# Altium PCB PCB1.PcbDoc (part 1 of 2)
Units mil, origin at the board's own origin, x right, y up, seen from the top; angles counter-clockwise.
Board outline 2130 x 2330 mil, 2 copper layers (Top Layer, Bottom Layer); 110 components, 79 nets, 324 pads, 362 vias.
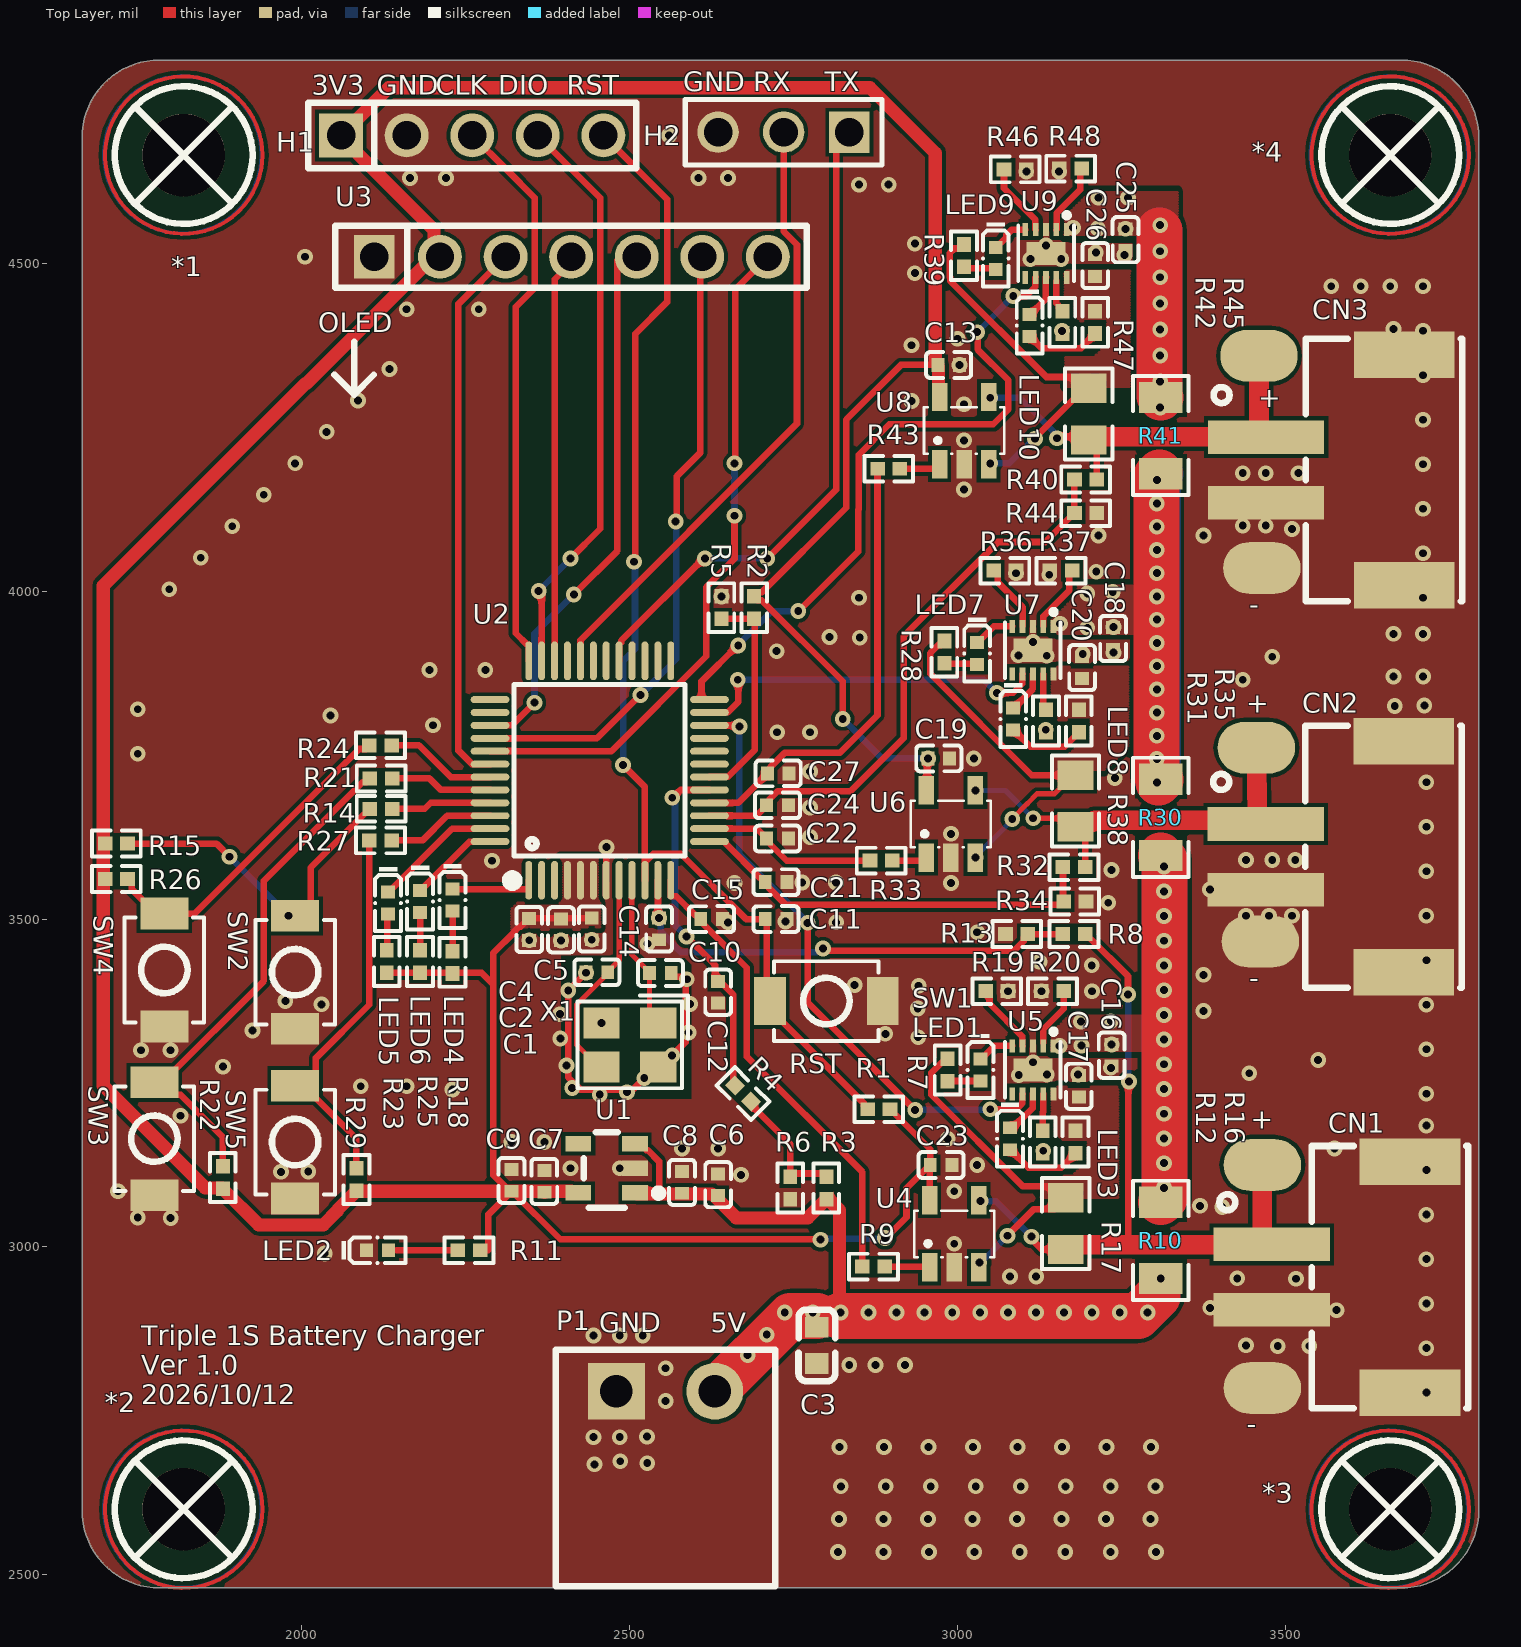
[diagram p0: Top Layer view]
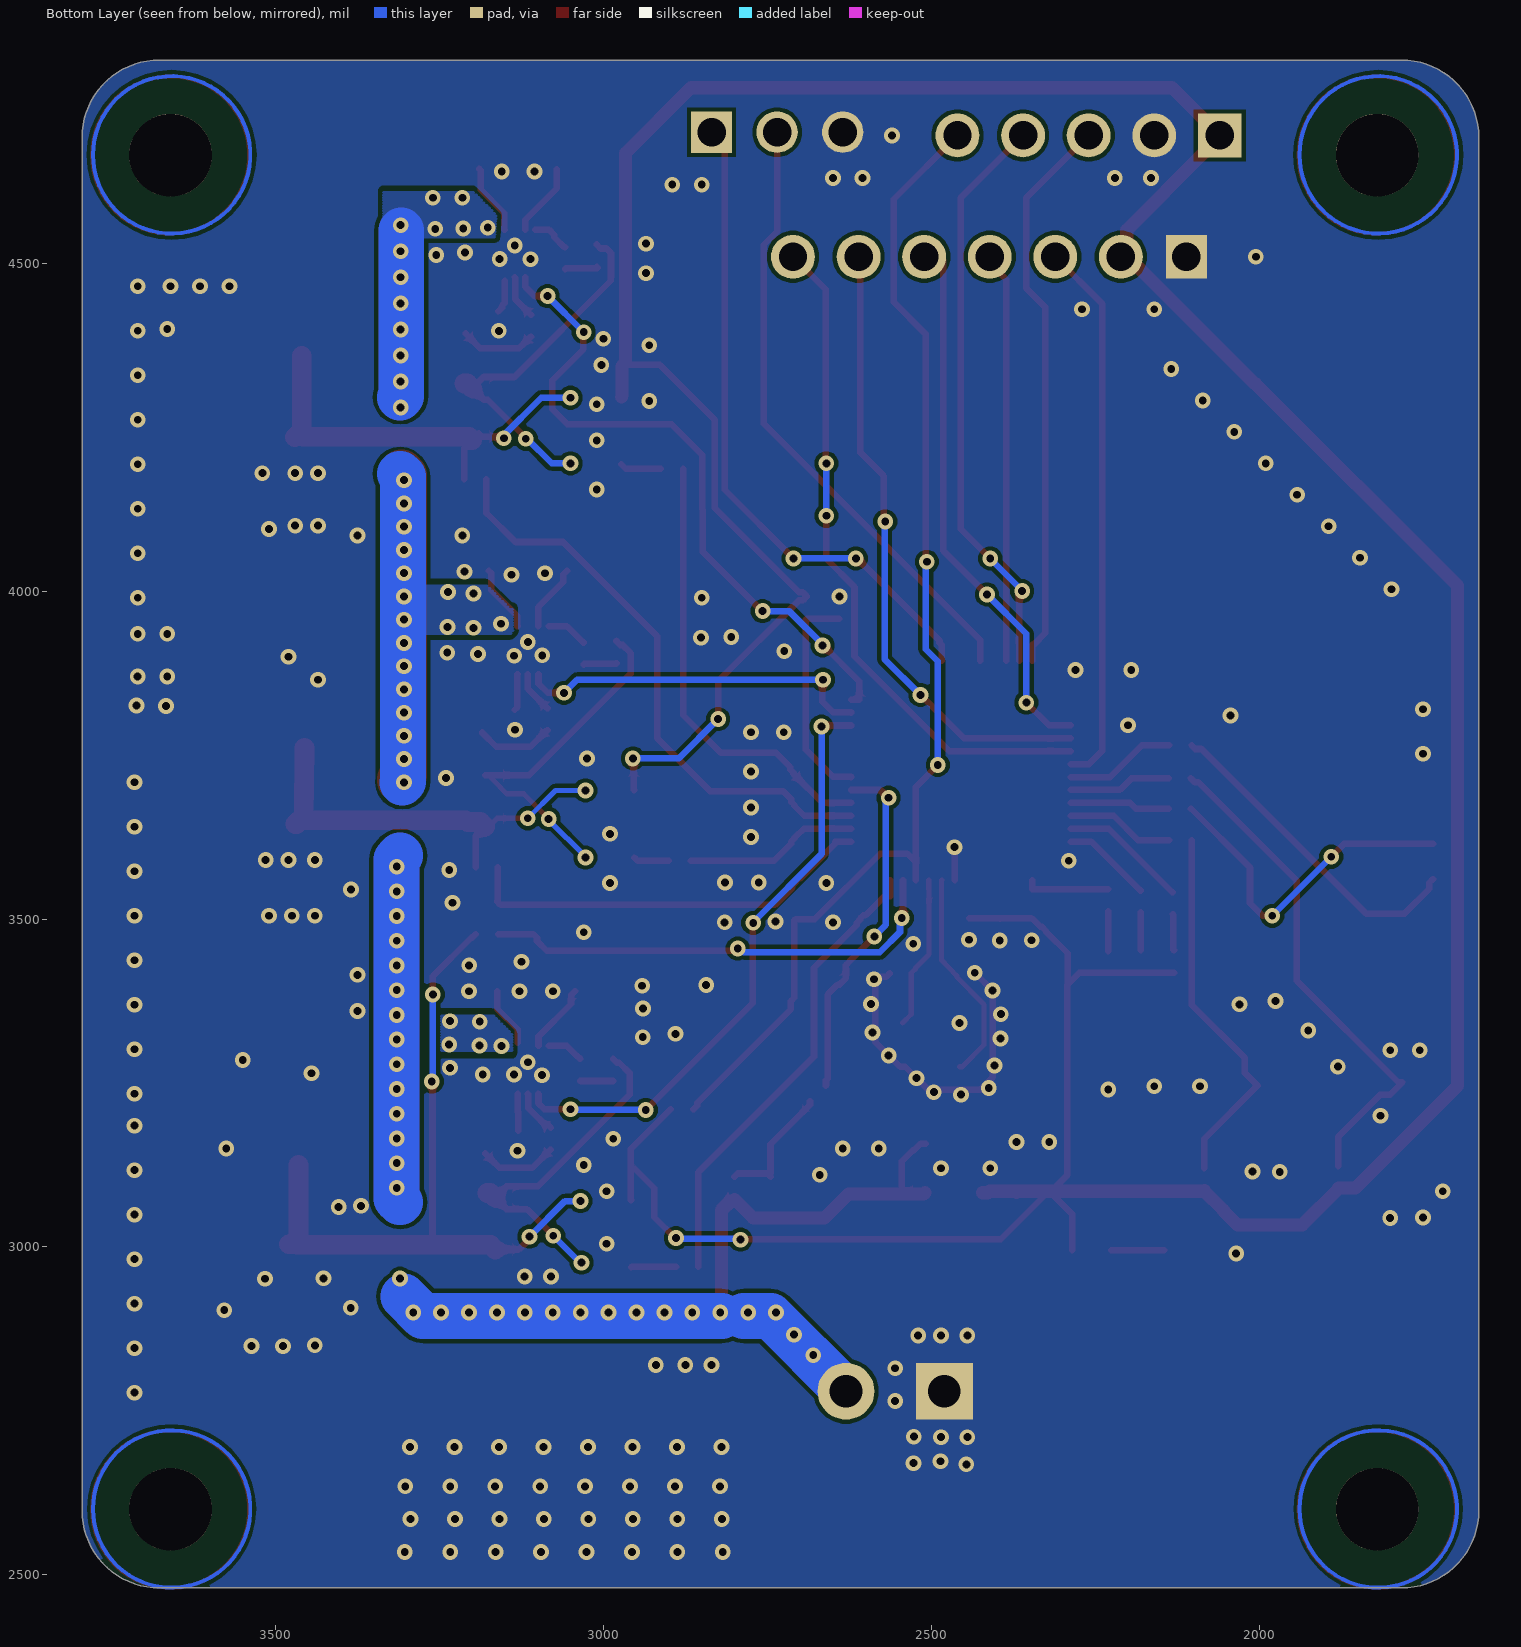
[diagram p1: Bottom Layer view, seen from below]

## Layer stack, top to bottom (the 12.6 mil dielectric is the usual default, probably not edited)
Top Solder: solder mask 0.4, Solder Resist, Dk 3.5
Top Layer: signal copper 1.4
Dielectric 1: dielectric 12.6, FR-4, Dk 4.8
Bottom Layer: signal copper 1.4
Bottom Solder: solder mask 0.4, Solder Resist, Dk 3.5

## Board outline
1665,2598.11 1665,4691.89 cw(c1783.11,4691.89) 1783.11,4810 3676.89,4810 cw(c3676.89,4691.89) 3795,4691.89 3795,2598.11 cw(c3676.89,2598.11) 3676.89,2480 1783.11,2480 cw(c1783.11,2598.11)

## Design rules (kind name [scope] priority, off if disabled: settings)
Clearance [All] p1: gap=6 ignorepadtopadclearanceinfootprint=FALSE except(4: Arc-Arc Arc-Track Track-Track; 6.9: Arc-Hole Track-Hole SMDPad-Hole THPad-Hole Via-Hole Fill-Hole Poly-Hole Region-Hole Text-Hole; 10: Fill-Text Poly-Text Region-Text)
ComponentClearance [All] p1: gap=0 collisioncheckmode=3 verticalgap=0 showdistances=FALSE
HoleSize [All] p1: absolutevalues=TRUE maxlimit=130 minlimit=1 maxpercent=80.000 minpercent=20.000
MinimumSolderMaskSliver [All] p1: minsoldermaskwidth=4
PlaneConnect [All] p1: planeconnectstyle=Direct reliefexpansion=20 reliefentries=4 reliefconductorwidth=10 reliefairgap=10
PolygonConnect [All] p1: connectstyle=Direct reliefconductorwidth=10 reliefentries=4 polygonreliefangle="90 Angle" airgapwidth=10
RoutingVias [All] p1: holewidth=28 width=50 viastyle="Through Hole" minholewidth=28 minwidth=50 maxholewidth=28 maxwidth=50
SilkToSilkClearance [All] p1: silktosilkclearance=2
SilkToSolderMaskClearance [IsPad] p1: minsilkscreentomaskgap=2 clearancetoexposedcopper=TRUE
SolderMaskExpansion [All] p1: expansion=0 istentingtop=FALSE
SupplyNets "Schematic Supply Nets_12" [InNet('5V_1')] p1: voltage=0.000
SupplyNets "Schematic Supply Nets_11" [InNet('5V_2')] p2: voltage=0.000
SupplyNets "Schematic Supply Nets_2" [InNet('5V_3')] p3: voltage=0.000
SupplyNets "Schematic Supply Nets_9" [InNet('VBAT3')] p4: voltage=0.000
SupplyNets "Schematic Supply Nets_6" [InNet('VBAT2')] p5: voltage=0.000
SupplyNets "Schematic Supply Nets_10" [InNet('VBAT3_H')] p6: voltage=0.000
SupplyNets "Schematic Supply Nets_7" [InNet('VBAT1_H')] p7: voltage=0.000
SupplyNets "Schematic Supply Nets_5" [InNet('VBAT1')] p8: voltage=0.000
SupplyNets "Schematic Supply Nets_4" [InNet('VBAT2_H')] p9: voltage=0.000
SupplyNets "Schematic Supply Nets_1" [InNet('5V')] p10: voltage=0.000
SupplyNets "Schematic Supply Nets" [InNet('3V3')] p11: voltage=0.000
SupplyNets "Schematic Supply Nets_8" [InNet('GND')] p12: voltage=0.000
Width [All] p1: maxlimit=120 minlimit=6 preferedwidth=10 minimp=50.000000 maximp=50.000000 favimp=50.000000
24 further rules are at their usual default settings.

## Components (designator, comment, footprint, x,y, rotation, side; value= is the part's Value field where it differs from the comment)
*1 "螺丝孔_1" M3螺丝 1820,4665 r0 top
*2 "螺丝孔_1" M3螺丝 1820,2600 r0 top
*3 "螺丝孔_1" M3螺丝 3660,2600 r0 top
*4 "螺丝孔_1" M3螺丝 3660,4665 r0 top
C1 "cc0402krx7r7bb104" C0402 2346.91,3484.19 r270 top value=100nF
C2 "cc0402krx7r7bb104" C0402 2395.45,3483.76 r270 top value=100nF
C3 "hgc0603r5226m160nthj" C0603 2785.56,2849.86 r90 top value=22uF
C4 "cc0402krx7r7bb104" C0402 2442.28,3485.04 r270 top value=100nF
C5 "cc0402jrnpo9bn180" C0402 2450.12,3418.96 r180 top value=18pF
C6 "cga0402x5r105k500gt" C0402 2635,3095 r90 top value=1uF
C7 "cc0402krx7r7bb104" C0402 2370,3100 r90 top value=100nF
C8 "cc0402krx7r7bb104" C0402 2580,3098.46 r90 top value=100nF
C9 "cga0402x5r105k500gt" C0402 2320,3101.54 r90 top value=1uF
C10 "cc0402jrnpo9bn180" C0402 2546.94,3417.73 r180 top value=18pF
C11 "cc0402krx7r7bb104" C0402 2723.36,3500 r180 top value=100nF
C12 "cc0402krx7r7bb104" C0402 2635,3388.46 r90 top value=100nF
C13 "cc0402krx7r7bb104" C0402 2986.54,4345 r180 top value=100nF
C14 "cc0402krx7r7bb104" C0402 2545,3485 r270 top value=100nF
C15 "cc0402krx7r7bb104" C0402 2625,3500 r0 top value=100nF
C16 "cga0402x5r105k500gt" C0402 3235.15,3292.39 r90 top value=1uF
C17 "cga0402x5r105k500gt" C0402 3185,3245 r270 top value=1uF
C18 "cga0402x5r105k500gt" C0402 3237.26,3927.95 r90 top value=1uF
C19 "cc0402krx7r7bb104" C0402 2971.54,3745 r180 top value=100nF
C20 "cga0402x5r105k500gt" C0402 3190,3883.46 r270 top value=1uF
C21 "cc0402krx7r7bb104" C0402 2723.36,3556.33 r0 top value=100nF
C22 "cc0402krx7r7bb104" C0402 2725.49,3622.82 r0 top value=100nF
C23 "cc0402krx7r7bb104" C0402 2975,3125 r180 top value=100nF
C24 "cc0402krx7r7bb104" C0402 2725.49,3673.63 r0 top value=100nF
C25 "cga0402x5r105k500gt" C0402 3256.34,4536 r90 top value=1uF
C26 "cga0402x5r105k500gt" C0402 3210,4496.54 r270 top value=1uF
C27 "cc0402krx7r7bb104" C0402 2726.58,3722.23 r0 top value=100nF
CN1 "2.54-2a-lt" CONN-SMD_2P-P2.54_XH2.54-2AB 3584.68,2954.02 r270 top
CN2 "2.54-2a-lt" CONN-SMD_2P-P2.54_XH2.54-2AB 3575.32,3595.03 r270 top
CN3 "2.54-2a-lt" CONN-SMD_2P-P2.54_XH2.54-2AB 3575.95,4184.87 r270 top
H1 "pz254v-11-05p" HDR-TH_5P-P2.54-V-M 2260,4695 r0 top
H2 "lail-pz2.54-3p-l" HDR-TH_3P-P2.54-V-M-1 2735,4700 r180 top
LED1 "xl-1005ugc_c965793" LED0402-RD_GREEN 3035,3270 r270 top
LED2 "xl-1005ugc_c965793" LED0402-RD_GREEN 2115.51,2994.99 r0 top
LED3 "xl-1005ugc_c965793" LED0402-RD_GREEN 3080,3165 r270 top
LED4 "xl-1005ugc_c965793" LED0402-RD_GREEN 2230,3528.91 r270 top
LED5 "xl-1005ugc_c965793" LED0402-RD_GREEN 2131.7,3524.28 r270 top
LED6 "xl-1005ugc_c965793" LED0402-RD_GREEN 2180.51,3526.83 r270 top
LED7 "xl-1005ugc_c965793" LED0402-RD_GREEN 3030,3905 r270 top
LED8 "xl-1005ugc_c965793" LED0402-RD_GREEN 3085,3805 r270 top
LED9 "xl-1005ugc_c965793" LED0402-RD_GREEN 3058.4,4507.47 r270 top
LED10 "xl-1005ugc_c965793" LED0402-RD_GREEN 3110,4405 r270 top
P1 "wj15edgrc-3.81-02p-14-00a" CONN-TH_2P-P3.81_WJ15EDGRC-3.81-2P 2555,2780 r0 top
R1 "frc0402f1002ts" R0402 2880,3210 r0 top value=10kΩ
R2 "frc0402f1002ts" R0402 2690,3975 r270 top value=10kΩ
R3 "frc0402f1003ts" R0402 2800,3090 r90 top value=100kΩ
R4 "frc0402j102 ts" R0402 2672.88,3233.98 r135 top value=1kΩ
R5 "ncp15xh103f03rc" R0402 2640,3975 r270 top
R6 "0402wgf4702tce" R0402 2745,3090 r90 top value=47kΩ
R7 "frc0402f1501ts" R0402 2985,3270 r90 top value=1.5kΩ
R8 "0402wgf4702tce" R0402 3177.55,3477.15 r180 top value=47kΩ
R9 "frc0402j102 ts" R0402 2872.04,2970 r180 top value=1kΩ
R10 "re1206f1r000" R1206 3310,3010 r270 top value=0Ω
R11 "frc0402j102 ts" R0402 2255,2995 r0 top value=1kΩ
R12 "frc0402f1002ts" R0402 3130,3160 r270 top value=10kΩ
R13 "frc0402f1002ts" R0402 3090.32,3477.15 r180 top value=10kΩ
R14 "0402wgf4700tce" R0402 2121.06,3668.18 r0 top value=470Ω
R15 "rc0402fr-074k7l" R0402 1717.33,3615.14 r0 top value=4.7kΩ
R16 "frc0402f1501ts" R0402 3180,3160 r90 top value=1.5kΩ
R17 "re0805far030" R0805 3165,3035.63 r270 top value=30mΩ
R18 "frc0402j102 ts" R0402 2230,3434.03 r270 top value=1kΩ
R19 "frc0402f2001ts" R0402 3060,3390 r180 top value=2kΩ
R20 "frc0402f5600ts" R0402 3145,3390 r0 top value=560Ω
R21 "0402wgf4700tce" R0402 2121.06,3714.5 r0 top value=470Ω
R22 "rc0402fr-074k7l" R0402 1879.63,3105.92 r90 top value=4.7kΩ
R23 "frc0402j102 ts" R0402 2129.65,3435.23 r270 top value=1kΩ
R24 "0402wgf4700tce" R0402 2120,3765 r0 top value=470Ω
R25 "frc0402j102 ts" R0402 2180.51,3435.23 r270 top value=1kΩ
R26 "rc0402fr-074k7l" R0402 1717.33,3561 r0 top value=4.7kΩ
R27 "0402wgf4700tce" R0402 2120,3620 r0 top value=470Ω
R28 "frc0402f1501ts" R0402 2980,3907.04 r90 top value=1.5kΩ
R29 "rc0402fr-074k7l" R0402 2083.42,3102.77 r90 top value=4.7kΩ
R30 "re1206f1r000" R1206 3310,3655 r270 top value=0Ω
R31 "frc0402f1002ts" R0402 3135,3802.04 r270 top value=10kΩ
R32 "0402wgf4702tce" R0402 3177.55,3579.11 r180 top value=47kΩ
R33 "frc0402j102 ts" R0402 2883.59,3589.12 r180 top value=1kΩ
R34 "frc0402f1002ts" R0402 3178.93,3526.83 r0 top value=10kΩ
R35 "frc0402f1501ts" R0402 3185,3802.04 r90 top value=1.5kΩ
R36 "frc0402f2001ts" R0402 3072.23,4031.28 r180 top value=2kΩ
R37 "frc0402f5600ts" R0402 3157.84,4031.28 r0 top value=560Ω
R38 "re0805far030" R0805 3180,3680 r270 top value=30mΩ
R39 "frc0402f1501ts" R0402 3010,4511.66 r90 top value=1.5kΩ
R40 "0402wgf4702tce" R0402 3195.41,4170.41 r180 top value=47kΩ
R41 "re1206f1r000" R1206 3310,4237.4 r270 top value=0Ω
R42 "frc0402f1002ts" R0402 3160,4410 r270 top value=10kΩ
R43 "frc0402j102 ts" R0402 2895.2,4186.76 r180 top value=1kΩ
R44 "frc0402f1002ts" R0402 3195.41,4119.02 r0 top value=10kΩ
R45 "frc0402f1501ts" R0402 3210,4410 r90 top value=1.5kΩ
R46 "frc0402f2001ts" R0402 3087.94,4643.25 r180 top value=2kΩ
R47 "re0805far030" R0805 3200,4270 r270 top value=30mΩ
R48 "frc0402f5600ts" R0402 3172.5,4644.45 r0 top value=560Ω
SW1 "ts-1088-ar02016" SW-SMD_L3.9-W3.0-P4.45 2800,3375 r180 top
SW2 "ts-1088-ar02016" SW-SMD_L3.9-W3.0-P4.45 1990,3418.96 r90 top
SW3 "ts-1088-ar02016" SW-SMD_L3.9-W3.0-P4.45 1775.37,3165.06 r90 top
SW4 "ts-1088-ar02016" SW-SMD_L3.9-W3.0-P4.45 1790.57,3422.39 r90 top
SW5 "ts-1088-ar02016" SW-SMD_L3.9-W3.0-P4.45 1990,3160 r90 top
U1 "tps7a2033pdbvr" SOT-23-5_L2.9-W1.6-P0.95-LS2.8-BR 2465,3120 r0 top
U2 "stm32g031c8t6" LQFP-48_L7.0-W7.0-P0.50-LS9.0-BL 2454.5,3726.46 r0 top
U3 "kh-2.54fh-1x7p-h8.5" HDR-TH_7P-P2.54-V-F 2410.85,4509.95 r0 top
U4 "ina180a3idbvr" SOT-23-5_L3.0-W1.7-P0.95-LS2.8-BR 2995,3020 r270 top
U5 "bq24040dsqr" WSON-10_L2.0-W2.0-P0.40-BL-EP 3115,3270 r180 top
U6 "ina180a3idbvr" SOT-23-5_L3.0-W1.7-P0.95-LS2.8-BR 2990,3645 r270 top
U7 "bq24040dsqr" WSON-10_L2.0-W2.0-P0.40-BL-EP 3115,3910 r180 top
U8 "ina180a3idbvr" SOT-23-5_L3.0-W1.7-P0.95-LS2.8-BR 3010,4245 r270 top
U9 "bq24040dsqr" WSON-10_L2.0-W2.0-P0.40-BL-EP 3135,4515 r180 top
X1 "x32258mob4si" CRYSTAL-SMD_4P-L3.2-W2.5-BL 2500.36,3308.16 r180 top value=8MHz

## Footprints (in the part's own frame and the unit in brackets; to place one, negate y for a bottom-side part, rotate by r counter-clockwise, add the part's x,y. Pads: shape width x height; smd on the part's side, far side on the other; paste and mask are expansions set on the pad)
C0402 [mm]
  rect 0.5x0.54 smd: 1(-0.42,0) 2(0.42,0)
  silkscreen extent -0.87,-0.5 0.87,0.5
C0603 [mm]
  rect 0.8x0.9 smd: 1(-0.7,0) 2(0.7,0)
  silkscreen extent -1.39,-0.71 1.39,0.71
CONN-SMD_2P-P2.54_XH2.54-2AB [mm]
  rect 1.3x4.5 smd: 1(-1.269,-2.675) 2(1.27,-2.675)
  rect 1.8x3.9 smd: 3(-4.47,2.675) 4(4.47,2.675)
  silkscreen extent -5.08,-4.71 5.08,4.93
CONN-TH_2P-P3.81_WJ15EDGRC-3.81-2P [mm]
  rect 2.2x2.2 hole 1.26: 1(-1.905,0)
  round 2.2 hole 1.26: 2(1.905,0)
  silkscreen extent -4.25,-7.55 4.25,1.6
CRYSTAL-SMD_4P-L3.2-W2.5-BL [mm]
  rect 1.4x1.2 smd: 1(-1.1,-0.85) 2(1.1,-0.85) 3(1.1,0.85) 4(-1.1,0.85)
  silkscreen extent -2.26,-1.91 2.03,1.68
HDR-TH_3P-P2.54-V-M-1 [mm]
  rect 1.575x1.6 hole 1.1 paste-2539.97 mask+0.05: 1(-2.54,0)
  round 1.6 hole 1.1 paste-2539.97 mask+0.05: 2(0,0) 3(2.54,0)
  silkscreen extent -3.81,-1.27 3.81,1.27
HDR-TH_5P-P2.54-V-M [mm]
  rect 1.7x1.7 hole 1.1: 1(-5.08,0)
  round 1.7 hole 1.1: 2(-2.54,0) 3(0,0) 4(2.54,0) 5(5.08,0)
  silkscreen extent -6.35,-1.27 6.35,1.27
HDR-TH_7P-P2.54-V-F [mm]
  rect 1.575x1.7 hole 1.1: 1(-7.62,0)
  round 1.7 hole 1.1: 2(-5.08,0) 3(-2.54,0) 4(0,0) 5(2.54,0) 6(5.08,0) 7(7.62,0)
  silkscreen extent -9.13,-1.2 9.13,1.2
LED0402-RD_GREEN [mm]
  rect 0.5x0.54 smd paste+0 mask+0.051: 1(-0.425,0) 2(0.425,0)
  silkscreen extent -1.39,-0.54 1.09,0.54
LQFP-48_L7.0-W7.0-P0.50-LS9.0-BL [mm]
  oval 0.27x1.5 smd paste+0 mask+0.05: 1(-2.75,-4.25) 2(-2.25,-4.25) 3(-1.75,-4.25) 4(-1.25,-4.25) 5(-0.75,-4.25) 6(-0.25,-4.25) 7(0.25,-4.25) 8(0.75,-4.25) 9(1.25,-4.25) 10(1.75,-4.25) 11(2.25,-4.25) 12(2.75,-4.25) 25(2.75,4.25) 26(2.25,4.25) 27(1.75,4.25) 28(1.25,4.25) 29(0.75,4.25) 30(0.25,4.25) 31(-0.25,4.25) 32(-0.75,4.25) 33(-1.25,4.25) 34(-1.75,4.25) 35(-2.25,4.25) 36(-2.75,4.25)
  oval 1.5x0.27 smd paste+0 mask+0.05: 13(4.25,-2.75) 14(4.25,-2.25) 15(4.25,-1.75) 16(4.25,-1.25) 17(4.25,-0.75) 18(4.25,-0.25) 19(4.25,0.25) 20(4.25,0.75) 21(4.25,1.25) 22(4.25,1.75) 23(4.25,2.25) 24(4.25,2.75) 37(-4.25,2.75) 38(-4.25,2.25) 39(-4.25,1.75) 40(-4.25,1.25) 41(-4.25,0.75) 42(-4.25,0.25) 43(-4.25,-0.25) 44(-4.25,-0.75) 45(-4.25,-1.25) 46(-4.25,-1.75) 47(-4.25,-2.25) 48(-4.25,-2.75)
  silkscreen extent -3.59,-4.46 3.3,3.34
M3螺丝 [mil]
  round 126 hole 126 paste-99999 mask+4: 1(0,0)
  Top Layer circle w6: c0,0 r120
  Bottom Layer circle w6: c-1.69,0.46 r120
  silkscreen extent -105,-105 105,105
R0402 [mm]
  rect 0.566x0.54 smd paste-100 mask+0.051: 1(-0.433,0) 2(0.433,0)
  silkscreen extent -0.94,-0.5 0.94,0.5
R0805 [mil]
  rect 44.59x54.21 smd paste-3937.01 mask+2: 1(-39.37,0) 2(39.37,0)
  silkscreen extent -69,-36 69,36
R1206 [mil]
  rect 47.54x66.97 smd paste-3937.01 mask+2: 1(-58.22,0) 2(58.22,0)
  silkscreen extent -91,-42 91,42
SOT-23-5_L2.9-W1.6-P0.95-LS2.8-BR [mm]
  rect 1x0.6 smd paste+0 mask+0.05: 1(1.1,-0.95) 2(1.1,0) 3(1.1,0.95) 4(-1.1,0.95) 5(-1.1,-0.95)
  silkscreen extent -0.89,-1.52 2.16,1.4
SOT-23-5_L3.0-W1.7-P0.95-LS2.8-BR [mm]
  rect 1.1x0.6 smd: 1(1.3,-0.95) 2(1.3,0) 3(1.3,0.95) 4(-1.3,0.95) 5(-1.3,-0.95)
  silkscreen extent -0.9,-1.55 0.9,1.55
SW-SMD_L3.9-W3.0-P4.45 [mm]
  rect 1.23x1.86 smd: 1(-2.185,0) 2(2.185,0)
  silkscreen extent -2.03,-1.54 2.03,1.54
WSON-10_L2.0-W2.0-P0.40-BL-EP [mm]
  rect 0.224x0.505 smd: 1(-0.8,-0.928) 2(-0.4,-0.928) 3(0,-0.928) 4(0.4,-0.928) 5(0.8,-0.928) 6(0.8,0.928) 7(0.4,0.928) 8(0,0.928) 9(-0.4,0.928) 10(-0.8,0.928)
  rect 1.5x0.9 smd: 11(0,0)
  silkscreen extent -1.08,-1.58 1.08,1.08

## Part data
C1 C2 C4 C7 C8 C11 C12 C13 C14 C15 C19 C21 C22 C23 C24 C27: "容值:100nF;精度:±10%;额定电压:16V;温度系数:X7R;", JLCPCB Part Class="Extended Part", LCSC Part Name="100nF ±10% 16V", Manufacturer=YAGEO(国巨), ManufacturerPart=CC0402KRX7R7BB104, Temperature Coefficient=X7R, Tolerance=±10%, Voltage Rating=16V
C3: "容值:22uF;精度:±20%;额定电压:16V;温度系数:X5R;", JLCPCB Part Class="Extended Part", LCSC Part Name="22uF ±20% 16V", Manufacturer=Chinocera(华瓷), ManufacturerPart=HGC0603R5226M160NTHJ, Temperature Coefficient=X5R, Tolerance=±20%, Voltage Rating=16V
C5 C10: "容值:18pF;精度:±5%;额定电压:50V;温度系数:NP0;", JLCPCB Part Class="Extended Part", LCSC Part Name="18pF ±5% 50V", Manufacturer=YAGEO(国巨), ManufacturerPart=CC0402JRNPO9BN180, Temperature Coefficient=NP0, Tolerance=±5%, Voltage Rating=50V
C6 C9 C16 C17 C18 C20 C25 C26: "容值:1uF;精度:±10%;额定电压:50V;温度系数:X5R;", JLCPCB Part Class="Extended Part", LCSC Part Name="1uF ±10% 50V", Manufacturer=HRE(芯声), ManufacturerPart=CGA0402X5R105K500GT, Temperature Coefficient=X5R, Tolerance=±10%, Voltage Rating=50V
CN1 CN2 CN3: "插针结构:1x2P;间距:2.54mm;安装方式:立贴;参考系列:XH;总PIN数:2P;排数:1;每排PIN数:2;行距:-;额定电流:500mA;触头材质:磷铜;触头镀层:锡;工作温度:-25℃~+85℃;", Color=米色, Current Rating=500mA, JLCPCB Part Class="Extended Part", LCSC Part Name="1x2P 间距:2.54mm 立贴 系列:XH", Manufacturer=CAX(创都), ManufacturerPart=2.54-2A-LT, Operating Temperature=-25℃~+85℃, Voltage Rating=50V
H1: "插针结构:1x5P;间距:2.54mm;行距:-;圆针/方针:方针;安装方式:直插;排数:单排;总PIN位数:5P;额定电流:3A;额定电压:250V;配合针长度:6mm;塑高:2.5mm;端接针长度:3mm;触头材质:黄铜;触头镀层:-;工作温度:-40℃~+105℃;颜色:黑色;", Color=黑色, Current Rating=3A, JLCPCB Part Class="Extended Part", LCSC Part Name="1x5P 间距:2.54mm 方针 直插", Manufacturer=XFCN(兴飞), ManufacturerPart=PZ254V-11-05P, Operating Temperature=-40℃~+105℃, Voltage Rating (Max)=250V
H2: "插针结构:1x3P;间距:2.54mm;圆针/方针:方针;排数:单排;总PIN位数:3P;额定电流:3A;额定电压:250V;塑高:2.5mm;端接针长度:3mm;触头材质:黄铜;触头镀层:金;工作温度:-25℃~+80℃;颜色:黑色;", Color=黑色, Current Rating=3A, JLCPCB Part Class="Extended Part", LCSC Part Name="1x3P 间距:2.54mm 方针", Manufacturer=LAILAN(莱联), ManufacturerPart=LAIL-PZ2.54-3P-L, Operating Temperature=-25℃~+80℃, Voltage Rating (Max)=250V
LED1 LED2 LED3 LED4 LED5 LED6 LED7 LED8 LED9 LED10: "灯头类型:1.0mmx0.5mm方形灯头;发光颜色:翠绿色;正向压降(Vf):3V;功率:80mW;正向电流:25mA;波长:516nm~531nm;二极管配置:独立二极管;透镜颜色:无色透明透镜;色温:-;发光强度:249mcd;发光角度:120°;载带方式:正贴;工作温度:-40℃~+85℃;", Color Temperature=-, Forward Current=25mA, Illumination Color=翠绿色, JLCPCB Part Class="Extended Part", LCSC Part Name=0402翠绿贴片式发光二极管, Lens Color=无色透明透镜, Manufacturer=XINGLIGHT(成兴光), ManufacturerPart=XL-1005UGC, Operating Temperature=-40℃~+85℃, Power(Watts)=80mW, Voltage - Forward(Vf)=3V
P1: "连接器类型:板端/插座-闭口;固定方式:无固定装置;结构:1x2P;间距:3.81mm;颜色:绿色;安装方式:弯插;排数:1;每排PIN数:2;额定电流:8A;额定电压:300V;线规 - AWG:-;线规 - 平方毫米:-;工作温度:-40℃~+105℃;", Color=绿色, Current Rating=8A, JLCPCB Part Class="Extended Part", LCSC Part Name="无固定装置 1x2P 3.81mm 排数:1 每排P数:2", Manufacturer=KANGNEX(康奈克斯电气), ManufacturerPart=WJ15EDGRC-3.81-02P-14-00A, Operating Temperature=-40℃~+105℃, Voltage Rating (Max)=300V
R1 R2 R12 R13 R31 R34 R42 R44: "电阻类型:厚膜电阻;阻值:10kΩ;精度:±1%;功率:62.5mW;工作电压:50V;温度系数:±100ppm/℃;", JLCPCB Part Class="Extended Part", LCSC Part Name="10kΩ ±1% 62.5mW 厚膜电阻", Manufacturer=FOJAN(富捷), ManufacturerPart=FRC0402F1002TS, Operating Temperature=-55℃~+155℃, Power(Watts)=62.5mW, Temperature Coefficient=±100ppm/℃, Tolerance=±1%, Voltage-Supply(Max)=50V
R3: "电阻类型:厚膜电阻;阻值:100kΩ;精度:±1%;功率:62.5mW;工作电压:50V;温度系数:±100ppm/℃;", JLCPCB Part Class="Extended Part", LCSC Part Name="100kΩ ±1% 62.5mW 厚膜电阻", Manufacturer=FOJAN(富捷), ManufacturerPart=FRC0402F1003TS, Operating Temperature=-55℃~+155℃, Power(Watts)=62.5mW, Temperature Coefficient=±100ppm/℃, Tolerance=±1%, Voltage-Supply(Max)=50V
R4 R9 R11 R18 R23 R25 R33 R43: "电阻类型:厚膜电阻;阻值:1kΩ;精度:±5%;功率:62.5mW;工作电压:50V;温度系数:±100ppm/℃;", JLCPCB Part Class="Extended Part", LCSC Part Name="1kΩ ±5% 62.5mW 厚膜电阻", Manufacturer=FOJAN(富捷), ManufacturerPart="FRC0402J102 TS", Operating Temperature=-55℃~+155℃, Power(Watts)=62.5mW, Temperature Coefficient=±100ppm/℃, Tolerance=±5%, Voltage-Supply(Max)=50V
R5: "阻值:10kΩ;B值(25℃/50℃):3380K;电阻精度:±1%;功率:100mW;B值精度:±1%;最大稳态电流(25℃):310uA;", B Constant Tolerance=±1%, JLCPCB Part Class="Extended Part", LCSC Part Name="10kΩ 3380K 100mW", Manufacturer=muRata(村田), ManufacturerPart=NCP15XH103F03RC, Operating Temperature=-40℃~+125℃, Power(Watts)=100mW, Resistance @ 25℃=10kΩ, Steady State Current (Max)=310uA
R6 R8 R32 R40: "电阻类型:厚膜电阻;阻值:47kΩ;精度:±1%;功率:62.5mW;工作电压:50V;温度系数:±100ppm/℃;", JLCPCB Part Class="Basic Part", LCSC Part Name="厚膜电阻 47kΩ ±1%", Manufacturer=UNI-ROYAL(厚声), ManufacturerPart=0402WGF4702TCE, Operating Temperature=-55℃~+155℃, Power(Watts)=62.5mW, Temperature Coefficient=±100ppm/℃, Tolerance=±1%, Voltage-Supply(Max)=50V
R7 R16 R28 R35 R39 R45: "电阻类型:厚膜电阻;阻值:1.5kΩ;精度:±1%;功率:62.5mW;工作电压:50V;温度系数:±100ppm/℃;", JLCPCB Part Class="Extended Part", LCSC Part Name="1.5kΩ ±1% 62.5mW 厚膜电阻", Manufacturer=FOJAN(富捷), ManufacturerPart=FRC0402F1501TS, Operating Temperature=-55℃~+155℃, Power(Watts)=62.5mW, Temperature Coefficient=±100ppm/℃, Tolerance=±1%, Voltage-Supply(Max)=50V
R10 R30 R41: "电阻类型:采样电阻；合金电阻;阻值:0Ω;精度:±1%;功率:1W;安装方式:贴片;", JLCPCB Part Class="Extended Part", LCSC Part Name="0Ω 1W 1206 ±1%", Manufacturer=JIERR(捷而瑞), ManufacturerPart=RE1206F1R000, Power(Watts)=1W, Tolerance=±1%
R14 R21 R24 R27: "电阻类型:厚膜电阻;阻值:470Ω;精度:±1%;功率:62.5mW;工作电压:50V;温度系数:±100ppm/℃;", JLCPCB Part Class="Basic Part", LCSC Part Name="厚膜电阻 470Ω ±1%", Manufacturer=UNI-ROYAL(厚声), ManufacturerPart=0402WGF4700TCE, Operating Temperature=-55℃~+155℃, Power(Watts)=62.5mW, Temperature Coefficient=±100ppm/℃, Tolerance=±1%, Voltage-Supply(Max)=50V
R15 R22 R26 R29: "电阻类型:厚膜电阻;阻值:4.7kΩ;精度:±1%;功率:62.5mW;工作电压:50V;温度系数:±100ppm/℃;", JLCPCB Part Class="Extended Part", LCSC Part Name="厚膜电阻 4.7kΩ ±1% 62.5mW", Manufacturer=YAGEO(国巨), ManufacturerPart=RC0402FR-074K7L, Operating Temperature=-55℃~+155℃, Power(Watts)=62.5mW, Temperature Coefficient=±100ppm/℃, Tolerance=±1%, Voltage-Supply(Max)=50V
R17 R38 R47: "电阻类型:合金电阻;阻值:30mΩ;精度:±1%;功率:500mW;温度系数:±50ppm/℃;安装方式:贴片;", JLCPCB Part Class="Extended Part", LCSC Part Name="30mΩ 0.5W 0805 ±1%", Manufacturer=JIERR(捷而瑞), ManufacturerPart=RE0805FAR030, Power(Watts)=500mW, Temperature Coefficient=±50ppm/℃, Tolerance=±1%
R19 R36 R46: "电阻类型:厚膜电阻;阻值:2kΩ;精度:±1%;功率:62.5mW;工作电压:50V;温度系数:±100ppm/℃;", JLCPCB Part Class="Extended Part", LCSC Part Name="2kΩ ±1% 62.5mW 厚膜电阻", Manufacturer=FOJAN(富捷), ManufacturerPart=FRC0402F2001TS, Operating Temperature=-55℃~+155℃, Power(Watts)=62.5mW, Temperature Coefficient=±100ppm/℃, Tolerance=±1%, Voltage-Supply(Max)=50V
R20 R37 R48: "电阻类型:厚膜电阻;阻值:560Ω;精度:±1%;功率:62.5mW;工作电压:50V;温度系数:±100ppm/℃;", JLCPCB Part Class="Extended Part", LCSC Part Name="560Ω ±1% 62.5mW 厚膜电阻", Manufacturer=FOJAN(富捷), ManufacturerPart=FRC0402F5600TS, Operating Temperature=-55℃~+155℃, Power(Watts)=62.5mW, Temperature Coefficient=±100ppm/℃, Tolerance=±1%, Voltage-Supply(Max)=50V
SW1 SW2 SW3 SW4 SW5: "电路结构:单刀单掷;按钮形状:圆形按钮;作用力:1.6N;安装方式:立贴;开关长度:3.9mm;开关宽度:3mm;开关高度:2mm;带支架:不带支架;触点电流:50mA;额定电压:12V;带灯:-;工作寿命:10万次;", Actuator/Cap Color=黑色, Contact Current=50mA, IP Rating=-, JLCPCB Part Class="Basic Part", LCSC Part Name="3.9*3*2mm 立贴 轻触开关", Manufacturer=XUNPU(讯普), ManufacturerPart=TS-1088-AR02016, Operating Force=1.6N, Operating Temperature=-30℃~+80℃, Voltage Rating=12V
U1: "输出类型:固定;最大输入电压:6V;输出电压:3.3V;输出电流:300mA;输出极性:正极;", Dropout Voltage=140mV@(300mA), JLCPCB Part Class="Extended Part", LCSC Part Name="具有高 PSRR 的 300mA、超低噪声、低 IQ、低压降 (LDO) 线性稳压器", Manufacturer=TI(德州仪器), ManufacturerPart=TPS7A2033PDBVR, Maximum Input Voltage=6V, Operating Temperature=-40℃~+125℃@(Tj), Output Current=300mA, Output Voltage=3.3V, standby current=15uA
U2: "CPU内核:ARM Cortex-M0+;CPU最大主频:64MHz;CPU位数:32 Bit;", JLCPCB Part Class="Extended Part", LCSC Part Name="主流Arm Cortex-M0+ MCU，具有64 KB Flash存储器、8 KB RAM、64 MHz CPU、2x USART、定时器、ADC和通信接口，1.7-3.6V", Manufacturer=ST(意法半导体), ManufacturerPart=STM32G031C8T6, Operating Temperature=-40℃~+85℃, Voltage - Supply=1.7V~3.6V
U3: "插孔结构:1x7P;间距:2.54mm;行距:-;圆孔/方孔:方孔;安装方式:直插;排数:单排;总孔位数:7P;额定电流:3A;额定电压:-;插孔方向:顶部;塑高:8.5mm;工作温度:-40℃~+105℃;", Current Rating=3A, JLCPCB Part Class="Extended Part", LCSC Part Name="间距:2.54mm 1x7P 直插", Manufacturer=kinghelm(金航标), ManufacturerPart=KH-2.54FH-1X7P-H8.5, Operating Temperature=-40℃~+105℃, Voltage Rating (Max)=-
U4 U6 U8: "放大器数:1;共模电压:-200mV~26V;增益:100V/V;带宽(-3db):150kHz;", Differential Voltage=±26V, Ib - Input Bias Current=100nA, Input Offset Voltage Drift(Vos TC)=1uV/℃, JLCPCB Part Class="Extended Part", LCSC Part Name=高低侧电压输出电流检测放大器, Manufacturer=TI(德州仪器), ManufacturerPart=INA180A3IDBVR, Operating Temperature=-40℃~+125℃, Output Current=8mA, Quiescent Current=197uA, Vcm - Common Mode Voltage=-200mV~26V, Vos - Input Offset Voltage=25uV
U5 U7 U9: "工作电压:3.5V~28V;最大充电电流:1A;电池类型:锂电池;电池节数:1;", Balance Current=-, Battery Temperature Detection=支持, Charge Current - Max=1A, Charging Saturation Voltage=4.2V, End-Off Voltage=800mV, JLCPCB Part Class="Extended Part", LCSC Part Name=1A单输入单节锂离子和锂聚合物电池充电器, Manufacturer=TI(德州仪器), ManufacturerPart=BQ24040DSQR, Operating Temperature=0℃~+125℃, Supply Current (Iq)=1mA, Voltage - Supply=3.5V~28V
X1: "晶振类型:贴片晶振;频率:8MHz;常温频差:±10ppm;负载电容:12pF;频率稳定度:±20ppm;", Equivalent Series Resistance(ESR)=180Ω, Frequency Stability=±20ppm, JLCPCB Part Class="Extended Part", LCSC Part Name="YSX321SL 8MHZ 4P 3225 12PF ±10PPM -40~85℃ (±20PPM)", Load Capacitance=12pF, Manufacturer=YXC(扬兴晶振), ManufacturerPart=X32258MOB4SI, Normal temperature Frequency Tolerance=±10ppm, Operating Temperature=-40℃~+85℃

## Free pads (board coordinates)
  oval 118.11x78.74 smd: 2(3455.86,3761.23) 2(3459.81,4359.02) 2(3462,3465.84) 2(3464.28,4035.33) 2(3465,2785) 2(3465,3125)

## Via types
v1: diameter 24, hole 12, Top Layer to Bottom Layer, tented both sides, 362 vias

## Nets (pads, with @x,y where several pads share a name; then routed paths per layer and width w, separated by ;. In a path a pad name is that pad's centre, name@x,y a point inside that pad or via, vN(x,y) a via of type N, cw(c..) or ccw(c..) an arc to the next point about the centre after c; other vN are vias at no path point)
3V3: C1.1 C2.1 C4.1 C7.1 C9.1 C13.2 C19.2 C23.2 H1.1 R1.2 R2.1 R11.2 R15.1 R18.2 R22.1 R23.2 R25.2 R26.1 R29.1 U1.5 U2.4 U2.5 U2.6 U3.2 U4.5 U6.5 U8.5 | length 6606.5
  Top Layer w10: R23.2@2129.65,3418.19 R25.2@2180.51,3418.19 2230,3418.19 2274.13,3418.19 2292.32,3400 2292.32,3109.73 2312.21,3089.84 C9.1@2314.37,3089.84 ; 2284.66,2995 2284.66,3049.66 2314.37,3079.37 C9.1@2314.37,3080.16 ; 2291.91,3400.42 2291.91,3447.74 2325.28,3481.12 2325.28,3482.05 2331.73,3488.49 2333.89,3488.49 2346.13,3500.73 C1.1@2346.91,3500.73 2347.34,3501.16 C2.1@2395.45,3501.16 ; C9.1@2315.71,3081.5 2319.21,3085 C9.1@2320,3085 ; C9.1@2320.79,3085 2394.18,3011.61 2784.58,3011.61 2787.72,3008.47 2787.72,3005.93 v1@2797.22,3015.43 ; C2.1@2395.45,3500.3 C2.1@2395.45,3501.16 ; C4.1@2442.28,3501.58 2441.85,3501.16 C2.1@2395.45,3501.16 ; R2.1@2690,3992.04 2690,3991.53 2695.63,3985.91 2701.66,3985.91 2825,3862.57 v1(2825,3805) ; R2.1@2690,3992.55 2695.63,3998.18 2701.28,3998.18 2830.46,4127.35 2830.46,4261.77 2913.69,4345 C13.2@2970,4345 ; v1@2889.42,3012.38 2922.28,3045.23 2922.28,3089.56 2952.09,3119.37 2953.62,3119.37 2957.72,3123.47 C23.2@2957.72,3125 ; R1.2@2897.55,3210 2958.46,3149.09 C23.2@2958.46,3125 2958.03,3124.57 2958.03,3071.62 U4.5@2957.6,3071.19 ; U6.5@2952.6,3696.19 2953.8,3697.39 2953.8,3743.8 v1(2955,3745)
  Top Layer w20: R22.1@1879.63,3088.38 1934.24,3033.77 2033.24,3033.77 2054.51,3055.03 2054.51,3056.31 2083.42,3085.23 R29.1@2083.42,3085.73 ; R22.1@1879.63,3088.88 1879.63,3089.39 1879,3090.01 1852.98,3090.01 1697.37,3245.63 1697.37,3561 1697.37,3615.14 1697.37,4008.35 2005.61,4316.59 2006.99,4316.59 2200.35,4509.95 U3.2@2210.85,4509.95 2201.87,4518.93 2201.87,4550.69 2083.46,4669.09 2083.46,4671.54 H1.1@2060,4695 2132.77,4767.77 2866.64,4767.77 2966.17,4668.24 C13.2@2966.17,4349.34 ; R29.1@2083.42,3085.63 2084.05,3085 C9.1@2320,3085 ; C9.1@2320.79,3085 C7.1@2370,3085 ; C7.1@2370,3083.46 C7.1@2370,3085 ; U1.5@2421.69,3082.59 2413.81,3082.59 2411.41,3085 C7.1@2370,3085 ; C13.2@2970,4345 2971.3,4343.7 2971.3,4297.48 U8.5@2972.6,4296.18
  Bottom Layer w10: v1@2790,3012.75 v1@2889.81,3012.75 ; v1(2825,3805) 2885,3745 v1(2955,3745)
  other v1: 2791.05,3011.2 2889.41,3013.52
5V: C3.2 C6.1 C8.1 P1.2 R3.1 R10.2 U1.1 U1.3 | length 2004.5
  Top Layer w10: U1.3@2508.31,3157.4 2516.18,3157.4 2525.77,3147.81 2527.55,3147.81 2545,3130.35 2545,3080.7 ; R3.1@2800,3072.45 2805.63,3066.82 R3.1@2809.22,3066.82
  Top Layer w20: U1.1@2509.47,3082.6 2511.28,3080.79 2527.47,3080.79 2527.57,3080.7 2545,3080.7 C8.1@2580,3080.7 ; C8.1@2580.91,3081.01 2625.9,3081.01 2662.58,3044.33 2771.88,3044.33 R3.1@2800,3072.45 ; R3.1@2809.22,3066.82 2819.85,3056.19 v1@2819.85,2894.6
  Top Layer w70: P1.2@2630,2779.6 2745,2894.6 v1@2785.56,2894.6 ; v1@2819.85,2894.6 3275,2894.6 3305,2924.6
  Bottom Layer w70: P1.2@2630,2779.6 2745,2894.6 v1@2785.56,2894.6 ; v1@2819.85,2894.6 3275,2894.6 3305,2924.6
  other v1: 2680,2835 2709.13,2866.3 2736.67,2900 2779.23,2900 2821.8,2900 2864.36,2900 2906.93,2900 2949.49,2900 2992.05,2900 3034.62,2900 3077.18,2900 3119.74,2900 3162.31,2900 3204.87,2900 3247.44,2900 3290,2900 3310,2951.78
5V_1: C16.2 R10.1 R30.2 U5.1 | length 1143.1
  Top Layer w30: 3296.31,3305 v1@3315.63,3285.68
  Top Layer w70: R10.1@3310,3068.22 3315.63,3073.85 3315.63,3127.82 3315.63,3165.5 3315.63,3203.19 3315.63,3240.87 3315.63,3285.68 3315.63,3308.93 v1@3315.63,3353.91 ; R30.2@3310,3596.78 3315.63,3591.15 3315.63,3542.32 3315.63,3504.64 3315.63,3466.95 3315.63,3429.27 3315.63,3391.59 v1@3315.63,3353.91 ; v1@3315.63,3304.54 v1@3315.63,3353.91
  Bottom Layer w70: 3310,3068.22 3315.63,3073.85 3315.63,3591.15 3310,3596.78
  other v1: 3315,3090.14 3315,3127.82 3315,3165.5 3315,3203.19 3315,3240.87 3315,3278.55 3155.45,3306.38 3189.05,3307.29 3235.15,3308.93 3315,3316.23 3188.44,3343.64 3233.88,3344.33 3315,3353.91 3315,3391.59 3315,3429.27 3315,3466.95 3315,3504.64 3315,3542.32 3315,3580
5V_2: C18.2 R30.1 R41.2 U7.1 | length 951.1
  Top Layer w70: R30.1@3306.76,3708.5 3310,3711.74 R30.1@3310,3713.22 3303.7,3719.52 3303.7,3810 3303.7,3848.74 3303.7,3915 3303.7,3944.49 3303.7,3951.53 3303.7,3992.09 3303.7,4027.54 3303.7,4062.99 3303.7,4098.44 3303.7,4133.89 3303.7,4176.32 R41.2@3308.14,4180.76
  Bottom Layer w70: v1@3306.76,3708.5 3305.56,3709.7 3305.56,3810 3305.56,3882.49 3305.56,3948.11 3305.56,3985 3305.56,4054.35 3305.56,4091.85 3305.56,4129.34 3305.56,4174.75 v1@3310,4179.18
  other v1: 3304.04,3708.5 3304.04,3743.95 3304.04,3779.4 3304.04,3814.85 3304.04,3850.3 3304.04,3885.75 3304.04,3921.2 3198.01,3944.14 3237.77,3945.47 3156.27,3950.44 3304.04,3956.64 3304.04,3992.09 3198.01,3996.49 3236.77,3998.81 3304.04,4027.54 3304.04,4062.99 3304.04,4098.44 3304.04,4133.89 3304.04,4169.34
